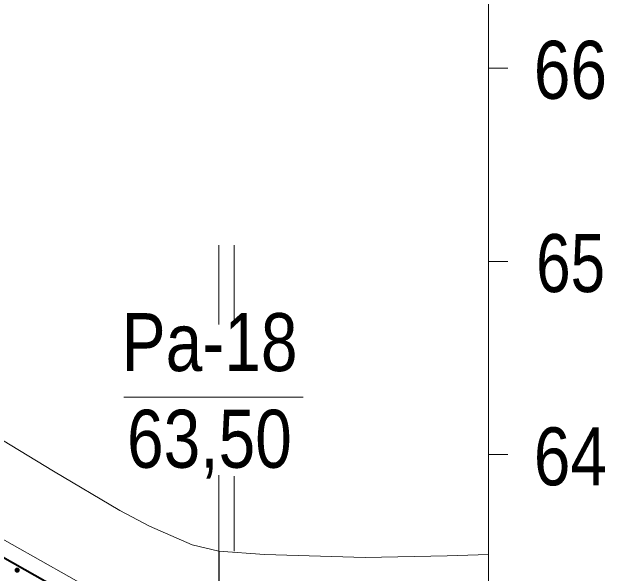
# Model space of a CAD drawing. Extents: x 640104 to 640970, y 6442278 to 6442689.
# Drawn here: x 640553.41 to 640584.12, y 6442354.62 to 6442383.66 of the extents above; entities that cross this region are included whole.
import ezdxf
from ezdxf.enums import TextEntityAlignment as Align

# ---------------------------------------------------------------- set-up
doc = ezdxf.new("R2010")
doc.units = 0
doc.header["$LTSCALE"] = 1.2
for name, color, linetype, lineweight in [('30', 7, 'Continuous', 13), ('31', 7, 'Continuous', 13), ('32', 7, 'Continuous', 25), ('35', 7, 'Continuous', 35), ('45', 7, 'Continuous', 13)]:
    doc.layers.add(name, color=color, linetype=linetype, lineweight=lineweight)

msp = doc.modelspace()

# ---------------------------------------------------------------- hatches: boundary and pattern name
at = {"layer": '45'}
msp.add_hatch(color=256, dxfattribs=at).paths.add_polyline_path([(640553.757, 6442354.844, 1), (640553.608, 6442354.696, 1)])

# ---------------------------------------------------------------- linework, layer by layer
at = {"layer": '30'}
for p, q in [((640578.08, 6442300.75), (640578.08, 6442460.75)), ((640578.08, 6442380.75), (640579.08, 6442380.75)), ((640578.08, 6442370.75), (640579.08, 6442370.75)), ((640578.08, 6442360.75), (640579.08, 6442360.75))]:
    msp.add_line(p, q, dxfattribs=at)
at = {"layer": '31'}
for points in [[(640472.22, 6442370.64), (640475.92, 6442369.03), (640480.13, 6442368.11), (640486.56, 6442368.13), (640490.81, 6442368.83), (640497.84, 6442370.15), (640502.36, 6442371.12), (640509.6, 6442371.47), (640514.96, 6442371.33), (640519.35, 6442370.64), (640522.55, 6442370.08), (640525.96, 6442369.1), (640529.03, 6442368.13), (640533.83, 6442366.46), (640541.42, 6442362.91), (640550.47, 6442357.76), (640557.82, 6442353.61), (640561.26, 6442351.7), (640562.79, 6442350.94), (640563.97, 6442350.8), (640569.82, 6442350.38), (640578.08, 6442350.26)], [(640552.93, 6442361.5), (640555.56, 6442359.89), (640559, 6442357.85), (640560.54, 6442357.05), (640562.74, 6442356.09), (640564.12, 6442355.75), (640566.48, 6442355.59), (640571.69, 6442355.43), (640575.94, 6442355.51), (640578.08, 6442355.59)]]:
    msp.add_lwpolyline(points, dxfattribs=at)
at = {"layer": '32', "lineweight": 13}
msp.add_line((640559.2, 6442363.73), (640568.49, 6442363.73), dxfattribs=at)
at = {"layer": '32'}
msp.add_line((640564.12, 6442355.75), (640564.12, 6442315.75), dxfattribs=at)
at = {"layer": '35', "lineweight": 13}
for p, q in [((640564.12, 6442367.49), (640564.12, 6442371.58)), ((640564.92, 6442367.68), (640564.92, 6442371.58)), ((640564.12, 6442355.75), (640564.12, 6442359.69)), ((640564.92, 6442355.75), (640564.92, 6442359.63))]:
    msp.add_line(p, q, dxfattribs=at)
at = {"layer": '35', "lineweight": 40}
msp.add_lwpolyline([(640461.31, 6442378.03), (640465.15, 6442374.93), (640468.48, 6442372.32), (640471.83, 6442369.94), (640475.67, 6442368.27), (640480.04, 6442367.31), (640486.63, 6442367.33), (640490.95, 6442368.04), (640498, 6442369.36), (640502.47, 6442370.33), (640509.61, 6442370.67), (640514.89, 6442370.53), (640519.22, 6442369.85), (640522.37, 6442369.3), (640525.73, 6442368.34), (640528.77, 6442367.37), (640533.53, 6442365.72), (640541.05, 6442362.2), (640550.07, 6442357.06), (640557.43, 6442352.91), (640560.88, 6442350.99), (640563.32, 6442349.78)], dxfattribs=at)
at = {"layer": '45'}
msp.add_circle((640553.683, 6442354.77), 0.105, dxfattribs=at)

# ---------------------------------------------------------------- texts
at = {"layer": '30'}
for s, width, p in [('66', 0.85, (640582.32, 6442379.16)), ('65', 0.8, (640582.33, 6442369.16)), ('64', 0.85, (640582.32, 6442359.16))]:
    msp.add_text(s, height=3, dxfattribs=dict(at, width=width)).set_placement(p, align=Align.CENTER)
at = {"layer": '32', "width": 0.85}
for s, p in [('Pa-18', (640563.645, 6442365.07)), ('63,50', (640563.635, 6442360.07))]:
    msp.add_text(s, height=3, dxfattribs=at).set_placement(p, align=Align.CENTER)

doc.saveas('drawing.dxf')
